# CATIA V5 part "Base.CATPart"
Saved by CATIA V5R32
Part number: Base
Bounding box of the stored display mesh (mm): x -32 to 32, y 0 to 144, z 0 to 52
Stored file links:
  D:\PROJECTS\Project 2022\CATIA V5 6R 2022\Resources\Part Files\c12_catia_v5_6r2022_prt\c12_catia_v5-6r2022 figr_12-19\Base.CATPart
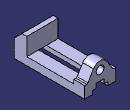
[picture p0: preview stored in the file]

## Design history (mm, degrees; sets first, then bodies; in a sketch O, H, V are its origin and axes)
Body1 (main body)
  Sketch1 on xy-plane, origin (0, 0, 0), H (1, 0, 0), V (0, 1, 0)
    point P1 (-32, 0)
    line L1 (-32, 0) -> (32, 0)
    line L2 (32, 0) -> (32, 144)
    line L3 (32, 144) -> (-32, 144)
    line L4 (-32, 144) -> (-32, 0)
    length L1 = 64
    length L2 = 144
    distance V L2 = 32
    coincidence: P1 H
    horizontal: L1 H, L3 H
    vertical: L2 V, L4 V
  Pad1: profile Sketch1, direction (0, 0, 1), length 16
  Sketch2 on face of Pad1, origin (32, 0, 0), H (0, 1, 0), V (0, 0, 1)
    point P1 (0, 16)
    line L1 (0, 16) -> (0, 36)
    point P2 (0, 36)
    line L2 (26, 52) -> (26, 16)
    line L3 (26, 16) -> (0, 16)
    reference projected line E1 (144, 16) -> (0, 16) from edge of Pad1
    line L4 (26, 52) -> (16, 52)
    point P5 (16, 52)
    line L5 (16, 52) -> (0, 36)
    length L2 = 36
    distance P5 P2 H = 16
    distance P5 P2 V = 16
    length L3 = 26
    coincidence: P1 V, E1 L3
    vertical: L1 V, L2 V
    horizontal: L3 H, L4 H
  Pad2: profile Sketch2, direction (-1, 0, 0), length 64
  Sketch3 on face of Pad1, origin (0, 144, 0), H (-1, 0, 0), V (0, 0, 1)
    line L1 (-32, 16) -> (-32, 24)
    point P2 (32, 24)
    line L2 (32, 24) -> (32, 16)
    line L3 (32, 16) -> (-32, 16)
    reference projected line E1 (32, 16) -> (-32, 16) from edge of Pad1
    line L4 (32, 24) -> (26, 24)
    point P4 (26, 24)
    line L5 (26, 24) -> (13.6777, 44.3018)
    point P5 (0, 52)
    line L6 (-13.6777, 44.3018) -> (-26, 24)
    point P6 (-26, 24)
    line L7 (-26, 24) -> (-32, 24)
    reference projected line E2 (32, 52) -> (-32, 52) from edge of Pad2
    reference projected line E3 (32, 16) -> (32, 52) from edge of Pad2
    reference projected line E4 (-32, 0) -> (-32, 16) from edge of Pad1
    arc A1 centre (0, 36) radius 16 from (13.6777, 44.3018) to (-13.6777, 44.3018) ccw
    point P8 (0, 36)
    reference projected line E5 (32, 52) -> (-32, 52) from edge of Pad2
    circle A2 centre (0, 36) radius 8
    distance H P2 = 24
    distance P6 P4 = 52
    distance P6 V = 26
    radius A1 = 16
    radius A2 = 8
    vertical: L1 V, L2 V
    horizontal: L3 H, L4 H, L7 H
    coincidence: L3 E1, P5 V, P6 L4, P5 E2, L2 E3, L1 E4, P8 V
    tangency: A1 E5, L6 A1, A1 L5
  Pad3: profile Sketch3, direction (0, -1, 0), length 22
  Fillet1: radius 3, on 2 edges
  Sketch4 on face of Pad1, origin (0, 144, 0), H (-1, 0, 0), V (0, 0, 1)
    point P1 (-16, 0)
    line L1 (-16, 0) -> (-16, 7)
    point P2 (-16, 7)
    line L2 (-16, 7) -> (-8, 7)
    point P3 (-8, 7)
    line L3 (-8, 7) -> (-8, 16)
    point P4 (-8, 16)
    line L4 (-8, 16) -> (0, 16)
    point P5 (0, 16)
    point P6 (16, 7)
    point P7 (16, 0)
    line L5 (16, 0) -> (16, 7)
    point P8 (8, 7)
    line L6 (16, 7) -> (8, 7)
    point P9 (8, 16)
    line L7 (8, 7) -> (8, 16)
    point P10 (0, 16)
    line L8 (8, 16) -> (0, 16)
    line L9 (-16, 0) -> (16, 0)
    point P11 (16, 0)
    distance L1 V = 16
    distance L3 V = 8
    distance H L4 = 16
    distance H L2 = 7
    coincidence: P1 H, P5 V, P7 P11, P5 P10
    vertical: L1 V, L3 V
    horizontal: L2 H, L4 H, L9 H
    symmetry: P2 P6 V, P1 P7 V, L1 L5 V, P3 P8 V, L2 L6 V, P4 P9 V, L3 L7 V, P5 P10 V, L4 L8 V
  Pocket1: profile Sketch4, direction (0, -1, 0), through (limit type 3)
  Sketch5 on face of Pad1, origin (0, 0, 0), H (1, 0, 0), V (0, -1, 0)
    circle A1 centre (22, -38) radius 3
    point P1 (22, -38)
    reference projected line E1 (32, 0) -> (-32, 0) from edge of Pad1
    radius A1 = 3
    distance P1 E1 = 38
    distance V P1 = 22
  Pocket2: profile Sketch5, direction (0, 0, 1), length 12
  RectPattern1: of Pocket2, direction 1 instances 2, spacing 70, along edge of Pad1, direction 2 instances 2, spacing 44, along edge of Pad1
